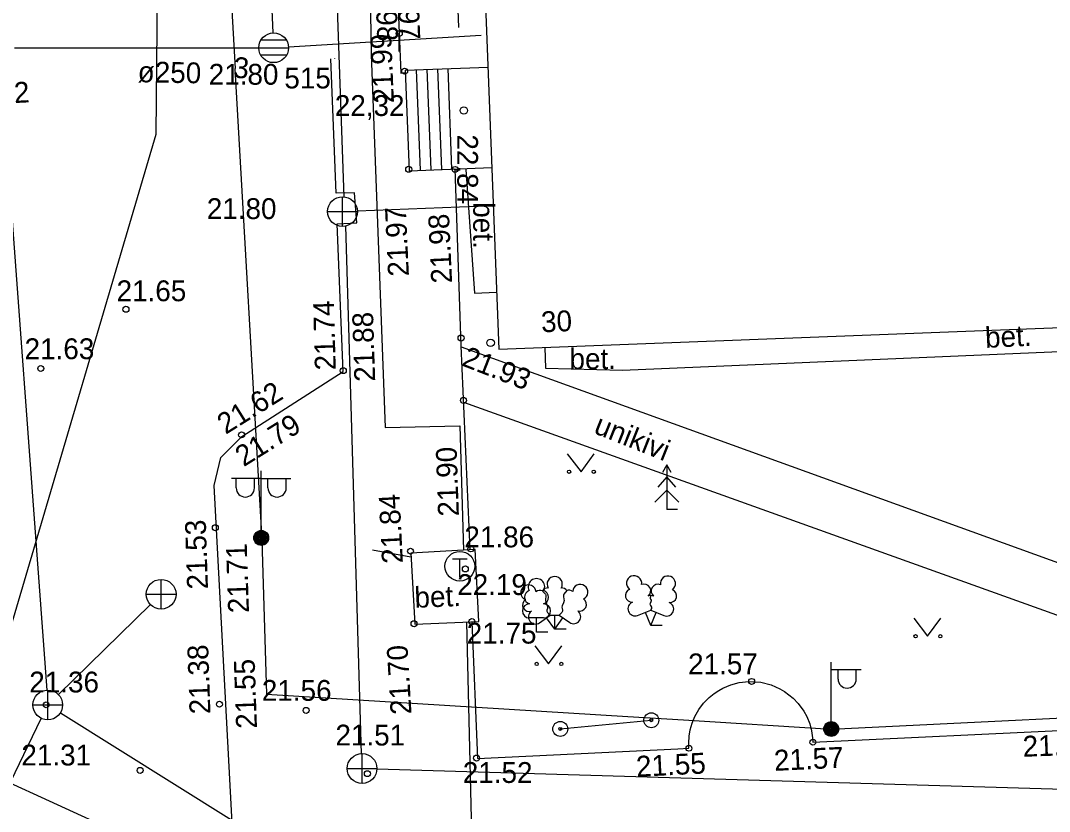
# Model space of a CAD drawing. Extents: x 714038 to 714279, y 6589845 to 6590041.
# Drawn here: x 714160.6 to 714195.16, y 6589960.57 to 6589987.15 of the extents above; entities that cross this region are included whole.
import ezdxf

# ---------------------------------------------------------------- set-up
doc = ezdxf.new("R2010")
doc.units = 0
for name, color, linetype in [('HALJASTUS', 7, 'Continuous'), ('HOONE', 7, 'Continuous'), ('HOONEDET', 7, 'Continuous'), ('KKAEV', 7, 'Continuous'), ('KORGUS', 7, 'Continuous'), ('KTRASS', 7, 'Continuous'), ('LIIKLUS', 7, 'Continuous'), ('MPKAABEL', 7, 'Continuous'), ('POST', 7, 'Continuous'), ('PUU', 7, 'Continuous'), ('SIKAEV', 7, 'Continuous'), ('SKKAEV', 7, 'Continuous'), ('SKTRASS', 7, 'Continuous'), ('TEE', 7, 'Continuous'), ('TKAEV', 7, 'Continuous'), ('TORU NR', 7, 'Continuous'), ('TTRASS', 7, 'Continuous'), ('VTRASS', 7, 'Continuous')]:
    doc.layers.add(name, color=color, linetype=linetype)

msp = doc.modelspace()

# ---------------------------------------------------------------- linework, layer by layer
at = {"layer": 'HALJASTUS'}
for p, q in [((714178.964, 6589972.594), (714179.428, 6589971.988)), ((714179.428, 6589971.988), (714179.873, 6589972.594)), ((714190.607, 6589967.067), (714191.07, 6589966.46)), ((714191.07, 6589966.46), (714191.516, 6589967.067)), ((714177.874, 6589966.135), (714178.338, 6589965.528)), ((714178.338, 6589965.528), (714178.783, 6589966.135))]:
    msp.add_line(p, q, dxfattribs=at)
for centre in [(714179.027, 6589971.988), (714179.856, 6589971.988), (714190.669, 6589966.46), (714191.498, 6589966.46), (714177.937, 6589965.528), (714178.765, 6589965.528)]:
    msp.add_circle(centre, 0.055, dxfattribs=at)
at = {"layer": 'HOONE'}
msp.add_lwpolyline([(714174.151, 6590040.965), (714175.285, 6590011.657), (714176.665, 6589976.107), (714220.25, 6589977.79), (714221.11, 6589977.83), (714221.8, 6589965.63), (714240.53, 6589966.47), (714239.93, 6589984.45), (714258.589, 6589985.264), (714256.524, 6590035.954)], dxfattribs=at)
at = {"layer": 'HOONEDET'}
for p, q in [((714173.52, 6589985.485), (714176.305, 6589985.59)), ((714173.52, 6589985.485), (714173.659, 6589982.106)), ((714174.031, 6589982.12), (714173.902, 6589985.499)), ((714174.389, 6589982.134), (714174.261, 6589985.513)), ((714174.748, 6589982.147), (714174.62, 6589985.526)), ((714175.091, 6589982.16), (714174.962, 6589985.539)), ((714173.659, 6589982.106), (714176.433, 6589982.211))]:
    msp.add_line(p, q, dxfattribs=at)
for points in [[(714175.018, 6589994.649), (714175.312, 6589986.916)], [(714178.211, 6589976.159), (714178.235, 6589975.468), (714180.826, 6589975.404), (714220.421, 6589977.091), (714221.034, 6589965.634)]]:
    msp.add_lwpolyline(points, dxfattribs=at)
at = {"layer": 'KKAEV'}
for p, q in [((714171.413, 6589980.231), (714171.413, 6589981.231)), ((714170.913, 6589980.731), (714171.913, 6589980.731)), ((714165.32, 6589967.37), (714165.32, 6589968.37)), ((714164.82, 6589967.87), (714165.82, 6589967.87)), ((714161.511, 6589963.65), (714161.511, 6589964.65)), ((714161.011, 6589964.15), (714162.011, 6589964.15)), ((714172.07, 6589961.514), (714172.07, 6589962.514)), ((714171.57, 6589962.014), (714172.57, 6589962.014))]:
    msp.add_line(p, q, dxfattribs=at)
for centre in [(714171.413, 6589980.731), (714165.32, 6589967.87), (714161.511, 6589964.15), (714172.07, 6589962.014)]:
    msp.add_circle(centre, 0.5, dxfattribs=at)
at = {"layer": 'KORGUS'}
for centre, radius in [((714173.321, 6589986.715), 0.1), ((714173.502, 6589985.45), 0.1), ((714175.49, 6589984.13), 0.125), ((714173.638, 6589982.153), 0.1), ((714175.196, 6589982.148), 0.1), ((714164.138, 6589977.448), 0.1), ((714175.396, 6589976.482), 0.1), ((714176.39, 6589976.32), 0.125), ((714161.276, 6589975.458), 0.1), ((714171.44, 6589975.385), 0.1), ((714175.478, 6589974.386), 0.1), ((714168.025, 6589973.228), 0.1), ((714167.142, 6589970.107), 0.1), ((714175.726, 6589969.395), 0.1), ((714173.698, 6589969.319), 0.1), ((714175.541, 6589968.722), 0.1), ((714175.76, 6589966.952), 0.1), ((714173.816, 6589966.881), 0.1), ((714185.16, 6589964.941), 0.1), ((714167.279, 6589964.175), 0.1), ((714161.458, 6589964.154), 0.1), ((714170.192, 6589963.968), 0.1), ((714187.217, 6589962.898), 0.1), ((714183.052, 6589962.696), 0.1), ((714175.918, 6589962.366), 0.1), ((714164.615, 6589961.952), 0.1), ((714172.249, 6589961.841), 0.1)]:
    msp.add_circle(centre, radius, dxfattribs=at)
at = {"layer": 'KTRASS'}
for points in [[(714170.858, 6589998.362), (714171.462, 6589981.232)], [(714176.482, 6589980.927), (714171.912, 6589980.75)], [(714172.055, 6589962.513), (714171.523, 6589980.241), (714171.522, 6589980.243)], [(714172.57, 6589962.002), (714218.72, 6589960.64)]]:
    msp.add_lwpolyline(points, dxfattribs=at)
at = {"layer": 'LIIKLUS'}
msp.add_line((714178.729, 6589963.345), (714181.787, 6589963.637), dxfattribs=at)
for centre, radius in [((714178.729, 6589963.345), 0.25), ((714181.787, 6589963.637), 0.25), ((714181.787, 6589963.637), 0.05), ((714178.729, 6589963.345), 0.05)]:
    msp.add_circle(centre, radius, dxfattribs=at)
at = {"layer": 'MPKAABEL'}
for points in [[(714167.029, 6589999.261), (714167.805, 6589985.535), (714167.801, 6589985.524), (714168.701, 6589969.69), (714168.856, 6589964.517), (714181.003, 6589963.765), (714182.873, 6589963.649), (714187.834, 6589963.342), (714201.122, 6589963.986), (714214.138, 6589964.636), (714217.634, 6589964.759), (714217.843, 6589958.743), (714218.335, 6589947.958), (714218.782, 6589937.076), (714219.871, 6589937.206), (714226.57, 6589937.936), (714228.214, 6589938.132), (714236.763, 6589938.683), (714246.845, 6589940.926), (714247.938, 6589921.303)], [(714123.717, 6589997.796), (714122.485, 6589997.244), (714122.51, 6589991.06), (714122.373, 6589988.225), (714122.093, 6589982.401), (714122.625, 6589980.577), (714131.807, 6589975.295), (714155.806, 6589963.558), (714167.836, 6589958.048), (714177.51, 6589953.25), (714191.113, 6589945.528), (714192.794, 6589944.261), (714190.81, 6589933.623), (714190.196, 6589929.064), (714190.863, 6589919.753), (714192.278, 6589911.176), (714192.96, 6589897.79), (714194.31, 6589864.41), (714194.86, 6589849.85), (714194.551, 6589845.18)], [(714167.8, 6589985.534), (714167.801, 6589985.524)]]:
    msp.add_lwpolyline(points, dxfattribs=at)
at = {"layer": 'POST'}
for p, q in [((714168.682, 6589970.015), (714168.682, 6589972.015)), ((714168.682, 6589971.765), (714167.682, 6589971.765)), ((714167.843, 6589971.444), (714167.843, 6589971.765)), ((714168.456, 6589971.444), (714168.456, 6589971.765)), ((714168.682, 6589971.765), (714169.682, 6589971.765)), ((714168.909, 6589971.444), (714168.909, 6589971.765)), ((714169.522, 6589971.444), (714169.522, 6589971.765)), ((714187.834, 6589963.592), (714187.834, 6589965.592)), ((714187.834, 6589965.342), (714188.834, 6589965.342)), ((714188.061, 6589965.021), (714188.061, 6589965.342)), ((714188.673, 6589965.021), (714188.673, 6589965.342))]:
    msp.add_line(p, q, dxfattribs=at)
for centre, radius in [((714168.682, 6589969.765), 0.25), ((714168.682, 6589969.765), 0.225), ((714168.682, 6589969.765), 0.2), ((714168.682, 6589969.765), 0.175), ((714168.682, 6589969.765), 0.15), ((714168.682, 6589969.765), 0.125), ((714168.682, 6589969.765), 0.1), ((714168.682, 6589969.765), 0.075), ((714168.682, 6589969.765), 0.05), ((714168.682, 6589969.765), 0.025), ((714187.834, 6589963.342), 0.25), ((714187.834, 6589963.342), 0.225), ((714187.834, 6589963.342), 0.2), ((714187.834, 6589963.342), 0.175), ((714187.834, 6589963.342), 0.15), ((714187.834, 6589963.342), 0.125), ((714187.834, 6589963.342), 0.1), ((714187.834, 6589963.342), 0.075), ((714187.834, 6589963.342), 0.05), ((714187.834, 6589963.342), 0.025)]:
    msp.add_circle(centre, radius, dxfattribs=at)
for centre in [(714168.149, 6589971.444), (714169.216, 6589971.444), (714188.367, 6589965.021)]:
    msp.add_arc(centre, 0.306, 180, 0, dxfattribs=at)
at = {"layer": 'PUU'}
for p, q in [((714182.309, 6589972.216), (714182.159, 6589971.966)), ((714182.459, 6589971.966), (714182.309, 6589972.216)), ((714182.309, 6589972.216), (714182.309, 6589970.716)), ((714182.309, 6589971.816), (714182.009, 6589971.466)), ((714182.609, 6589971.466), (714182.309, 6589971.816)), ((714182.309, 6589971.366), (714181.909, 6589970.966)), ((714182.709, 6589970.966), (714182.309, 6589971.366)), ((714182.669, 6589970.716), (714182.309, 6589970.716)), ((714178.171, 6589967.075), (714177.691, 6589967.075)), ((714177.931, 6589966.6), (714177.931, 6589967.075)), ((714178.033, 6589966.912), (714178.393, 6589967.167)), ((714178.543, 6589966.692), (714178.268, 6589967.077)), ((714178.393, 6589967.167), (714178.688, 6589967.167)), ((714178.543, 6589966.692), (714178.543, 6589967.167)), ((714178.543, 6589966.692), (714178.813, 6589967.082)), ((714178.688, 6589967.167), (714179.048, 6589966.922)), ((714181.328, 6589967.158), (714181.773, 6589967.333)), ((714181.768, 6589966.823), (714181.593, 6589967.263)), ((714181.768, 6589966.823), (714181.948, 6589967.263)), ((714181.773, 6589967.333), (714182.213, 6589967.153)), ((714178.923, 6589966.692), (714178.543, 6589966.692)), ((714182.148, 6589966.823), (714181.768, 6589966.823)), ((714178.311, 6589966.6), (714177.931, 6589966.6))]:
    msp.add_line(p, q, dxfattribs=at)
for points in [[(714178.131, 6589967.98), (714178.233, 6589967.877), (714178.248, 6589967.847), (714178.248, 6589967.792), (714178.233, 6589967.702), (714178.233, 6589967.657), (714178.253, 6589967.577), (714178.293, 6589967.487), (714178.303, 6589967.442), (714178.298, 6589967.397), (714178.283, 6589967.332), (714178.283, 6589967.302), (714178.303, 6589967.262), (714178.328, 6589967.232), (714178.393, 6589967.167)], [(714178.947, 6589967.994), (714178.853, 6589967.877), (714178.838, 6589967.847), (714178.838, 6589967.792), (714178.853, 6589967.702), (714178.858, 6589967.657), (714178.838, 6589967.577), (714178.798, 6589967.487), (714178.788, 6589967.442), (714178.793, 6589967.397), (714178.808, 6589967.332), (714178.808, 6589967.302), (714178.788, 6589967.262), (714178.763, 6589967.232), (714178.693, 6589967.167)], [(714181.773, 6589967.828), (714181.753, 6589967.753), (714181.753, 6589967.733), (714181.763, 6589967.703), (714181.783, 6589967.668), (714181.788, 6589967.648), (714181.773, 6589967.613), (714181.748, 6589967.563), (714181.743, 6589967.538), (714181.748, 6589967.523), (714181.758, 6589967.493), (714181.793, 6589967.433), (714181.798, 6589967.413), (714181.793, 6589967.393), (714181.778, 6589967.358), (714181.773, 6589967.333)]]:
    msp.add_lwpolyline(points, dxfattribs=at)
for centre, radius, start, end in [((714178.543, 6589968.212), 0.256, 90.0013, 211.0159), ((714178.543, 6589968.212), 0.256, 328.9841, 89.9987), ((714181.211, 6589968.238), 0.256, 111.5027, 232.5173), ((714181.211, 6589968.238), 0.256, 350.4856, 111.5002), ((714182.347, 6589968.229), 0.256, 67.6168, 188.6314), ((714182.347, 6589968.229), 0.256, 306.5997, 67.6143), ((714177.66, 6589967.929), 0.256, 125.5389, 246.5536), ((714177.66, 6589967.929), 0.256, 4.5218, 125.5364), ((714177.931, 6589968.12), 0.277, 332.5799, 207.4201), ((714178.306, 6589967.88), 0.202, 84.7965, 150.2995), ((714178.781, 6589967.88), 0.202, 34.3857, 95.2035), ((714179.404, 6589967.945), 0.256, 55.522, 176.5367), ((714179.404, 6589967.945), 0.256, 294.5049, 55.5195), ((714181.546, 6589967.987), 0.224, 308.5041, 111.5725), ((714182.009, 6589967.983), 0.225, 67.7016, 230.5126), ((714177.761, 6589967.772), 0.233, 109.0217, 253.1415), ((714178.046, 6589967.797), 0.202, 65.2382, 130.7412), ((714178.101, 6589967.772), 0.233, 286.8508, 70.9859), ((714179.02, 6589967.806), 0.202, 50.3173, 111.1351), ((714181.138, 6589967.826), 0.224, 111.4304, 274.4987), ((714181.772, 6589967.591), 0.237, 66.7655, 111.5015), ((714182.415, 6589967.816), 0.224, 264.6183, 67.6866), ((714177.694, 6589967.312), 0.238, 90.0016, 269.3953), ((714177.688, 6589967.512), 0.224, 125.4667, 288.5349), ((714178.169, 6589967.312), 0.238, 270.6047, 89.9984), ((714179.383, 6589967.528), 0.224, 252.5235, 55.5918), ((714181.242, 6589967.382), 0.237, 111.5014, 291.5004), ((714182.303, 6589967.374), 0.237, 247.6166, 67.6155), ((714177.897, 6589967.107), 0.237, 125.5377, 305.5366), ((714179.181, 6589967.118), 0.237, 235.5219, 55.5208)]:
    msp.add_arc(centre, radius, start, end, dxfattribs=at)
at = {"layer": 'SKKAEV'}
for p, q in [((714169.531, 6589986.487), (714168.671, 6589986.487)), ((714168.601, 6589986.237), (714169.601, 6589986.237)), ((714169.531, 6589985.987), (714168.671, 6589985.987))]:
    msp.add_line(p, q, dxfattribs=at)
msp.add_circle((714169.101, 6589986.237), 0.5, dxfattribs=at)
at = {"layer": 'SKTRASS'}
for points in [[(714169.079, 6589986.737), (714168.979, 6589989.053)], [(714169.6, 6589986.267), (714176.067, 6589986.655)], [(714160.39, 6589986.234), (714168.601, 6589986.237)], [(714159.92, 6589985.735), (714161.475, 6589964.649)], [(714164.962, 6589967.521), (714161.869, 6589964.499)], [(714159.079, 6589959.14), (714161.293, 6589963.7)], [(714161.935, 6589963.885), (714185.098, 6589949.388), (714203.298, 6589938.638), (714203.3, 6589938.638)]]:
    msp.add_lwpolyline(points, dxfattribs=at)
at = {"layer": 'TEE'}
for points in [[(714174.451, 6589994.627), (714172.996, 6589994.554), (714173.376, 6589985.388), (714173.524, 6589985.404)], [(714173.313, 6589986.11), (714173.321, 6589986.715)], [(714195.768, 6589942.431), (714184.455, 6589948.554), (714182.951, 6589949.081), (714178.977, 6589949.797), (714170.686, 6589954.288), (714169.092, 6589955.445), (714168.184, 6589956.63), (714167.808, 6589958.298), (714167.098, 6589971.521), (714167.324, 6589972.468), (714168.034, 6589973.172), (714171.434, 6589975.354), (714171.239, 6589980.323), (714171.896, 6589980.348), (714171.817, 6589981.365), (714171.201, 6589981.347), (714171.023, 6589985.866)], [(714170.999, 6589985.864), (714170.999, 6589985.87)], [(714171.149, 6589985.886), (714171.149, 6589985.88)], [(714175.708, 6589969.362), (714175.405, 6589976.216), (714175.2, 6589982.164)], [(714175.555, 6589982.144), (714175.848, 6589977.993), (714176.592, 6589978.021)], [(714175.406, 6589976.189), (714209.316, 6589963.923)], [(714204.994, 6589963.729), (714175.489, 6589974.311)], [(714175.866, 6589969.371), (714173.704, 6589969.247), (714173.845, 6589966.865), (714175.998, 6589966.95), (714175.866, 6589969.371)], [(714175.763, 6589966.941), (714175.945, 6589962.35), (714182.679, 6589962.679), (714183.052, 6589962.696), (714183.046, 6589962.867), (714183.06, 6589963.101), (714183.097, 6589963.312), (714183.161, 6589963.539), (714183.254, 6589963.764), (714183.39, 6589964.003), (714183.547, 6589964.212), (714183.728, 6589964.398), (714183.898, 6589964.537), (714184.052, 6589964.64), (714184.194, 6589964.718), (714184.458, 6589964.829), (714184.741, 6589964.904), (714185.063, 6589964.94), (714185.463, 6589964.915), (714185.812, 6589964.827), (714186.112, 6589964.696), (714186.266, 6589964.606), (714186.554, 6589964.381), (714186.725, 6589964.202), (714186.911, 6589963.944), (714187.011, 6589963.759), (714187.109, 6589963.52), (714187.173, 6589963.282), (714187.209, 6589963.041), (714187.217, 6589962.898), (714196.207, 6589963.323)]]:
    msp.add_lwpolyline(points, dxfattribs=at)
at = {"layer": 'TKAEV'}
for p, q in [((714175.107, 6589969.061), (714175.607, 6589969.061)), ((714175.357, 6589968.461), (714175.357, 6589969.061))]:
    msp.add_line(p, q, dxfattribs=at)
msp.add_circle((714175.357, 6589968.811), 0.5, dxfattribs=at)
at = {"layer": 'TTRASS'}
for points in [[(714171.653, 6590030.531), (714172.374, 6589986.01), (714172.85, 6589973.48), (714175.36, 6589973.53), (714175.475, 6589969.349)], [(714173.712, 6589969.115), (714172.418, 6589969.353)], [(714175.584, 6589966.934), (714175.81, 6589957.03), (714179.175, 6589955.169)]]:
    msp.add_lwpolyline(points, dxfattribs=at)
at = {"layer": 'VTRASS'}
msp.add_lwpolyline([(714166.254, 6590040.965), (714165.506, 6590022.329), (714165.378, 6590008.723), (714165.284, 6589998.807), (714165.141, 6589983.322), (714160.198, 6589966.563), (714155.909, 6589952.01), (714153.798, 6589949.498)], dxfattribs=at)

# ---------------------------------------------------------------- texts
at = {"layer": 'HOONE'}
msp.add_text('30', height=0.7, rotation=2.582, dxfattribs=at).set_placement((714178.1, 6589976.672))
at = {"layer": 'HOONEDET'}
for rotation, p in [(270, (714175.806, 6589981.045)), (0.2806, (714179.041, 6589975.432)), (2.3866, (714173.845, 6589967.412))]:
    msp.add_text('bet.', height=0.7, rotation=rotation, dxfattribs=at).set_placement(p)
at = {"layer": 'KORGUS'}
for s, rotation, p in [(' 21.98', 272.3741, (714172.479, 6589989.04)), (' 21.97', 272.3741, (714173.222, 6589989.093)), (' 21.99', 92.3849, (714173.154, 6589984.123)), (' 21.72', 3.1005, (714158.315, 6589984.264)), ('22,84', 270.1177, (714175.266, 6589983.324)), (' 21.97', 92.6468, (714173.659, 6589978.308)), (' 21.98', 92.6627, (714175.11, 6589978.073)), (' 21.74', 91.5863, (714171.196, 6589975.146)), (' 21.88', 91.8576, (714172.522, 6589974.767)), (' 21.93', 338.6756, (714175.141, 6589975.665)), (' 21.62', 32.03, (714167.268, 6589973.088)), (' 21.79', 32.03, (714167.874, 6589972)), (' 21.90', 91.9411, (714175.335, 6589970.236)), (' 21.84', 92.9074, (714173.458, 6589968.66)), (' 21.53 ', 91.8841, (714166.904, 6589967.786)), (' 21.71', 91.8841, (714168.282, 6589966.99)), (' 21.38 ', 91.9884, (714166.988, 6589963.591)), (' 21.70', 93.4319, (714173.75, 6589963.586)), (' 21.55', 91.9884, (714168.551, 6589963.106)), (' 21.62', 2.0486, (714194.017, 6589962.398)), (' 21.55', 2.9236, (714181.035, 6589961.719)), (' 21.57', 2.7574, (714185.668, 6589961.921))]:
    msp.add_text(s, height=0.7, rotation=rotation, dxfattribs=at).set_placement(p)
for s, p in [(' 21.80', (714166.659, 6589984.995)), ('22,32', (714171.156, 6589983.945)), (' 21.80', (714166.594, 6589980.48)), (' 21.65 ', (714163.563, 6589977.719)), (' 21.63', (714160.473, 6589975.771)), (' 21.86', (714175.248, 6589969.449)), (' 22.19', (714175.007, 6589967.846)), (' 21.75', (714175.327, 6589966.213)), (' 21.57', (714182.764, 6589965.181)), (' 21.36', (714160.63, 6589964.57)), (' 21.56', (714168.444, 6589964.29)), (' 21.51', (714170.917, 6589962.788)), (' 21.31', (714160.365, 6589962.116)), (' 21.52', (714175.195, 6589961.53))]:
    msp.add_text(s, height=0.7, dxfattribs=at).set_placement(p)
at = {"layer": 'SIKAEV'}
msp.add_text('515', height=0.7, dxfattribs=at).set_placement((714169.46, 6589984.87))
at = {"layer": 'TEE'}
for s, rotation, p in [('bet.', 2.7396, (714193.017, 6589976.148)), ('unikivi', 338.2736, (714179.819, 6589973.298))]:
    msp.add_text(s, height=0.7, rotation=rotation, dxfattribs=at).set_placement(p)
at = {"layer": 'TORU NR'}
for s, rotation, p in [('ø250', 358.8423, (714164.528, 6589985.082)), ('3', 354.7103, (714167.721, 6589985.24))]:
    msp.add_text(s, height=0.7, rotation=rotation, dxfattribs=at).set_placement(p)

doc.saveas('drawing.dxf')
